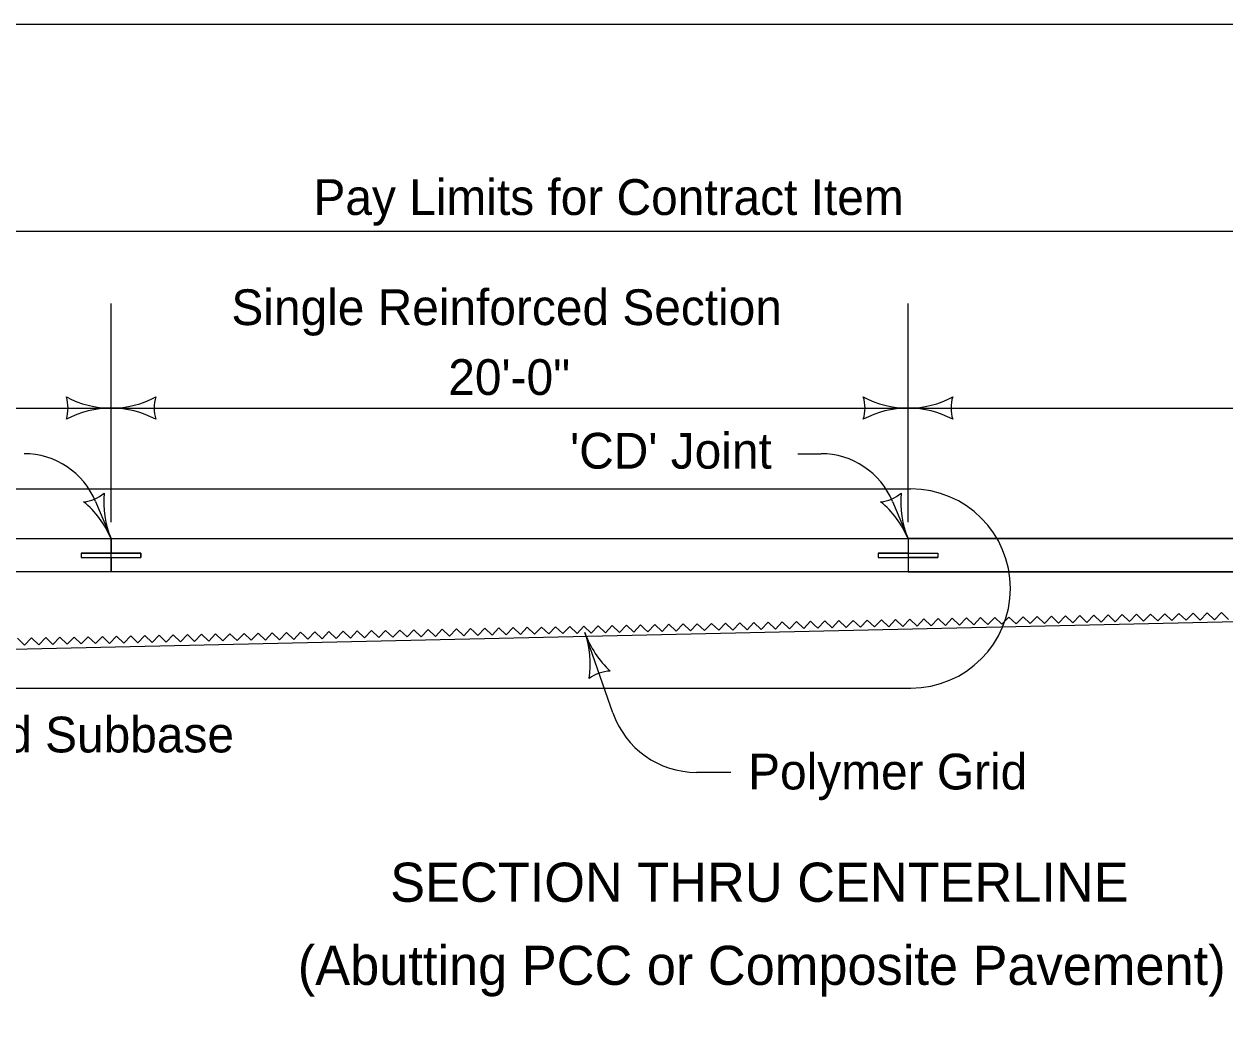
# Model space of a CAD drawing. Extents: x -2135039 to -2124495, y -2139046 to -2132546.
# Drawn here: x -2130571 to -2130034, y -2133467 to -2133016 of the extents above; entities that cross this region are included whole.
import ezdxf

# ---------------------------------------------------------------- set-up
doc = ezdxf.new("R2010")
doc.units = 0
for name, color, linetype in [('BridgeSuperStructureExisting', 7, 'Continuous'), ('dsnAlignmentStation', 7, 'Continuous'), ('dsnCellElements', 7, 'Continuous'), ('dsnStdLabel', 7, 'Continuous')]:
    doc.layers.add(name, color=color, linetype=linetype)

msp = doc.modelspace()

# ---------------------------------------------------------------- linework, layer by layer
at = {"layer": 'BridgeSuperStructureExisting'}
for p, q in [((-2130538.96, -2133229.57), (-2130532.03, -2133246.22)), ((-2130182.56, -2133229.57), (-2130175.63, -2133246.22)), ((-2130977.53, -2133246.22), (-2129822.62, -2133246.22)), ((-2130532.03, -2133261.07), (-2130532.03, -2133246.22)), ((-2129822.62, -2133246.22), (-2130175.63, -2133246.22)), ((-2130175.63, -2133246.22), (-2130175.63, -2133252.72)), ((-2130175.63, -2133246.22), (-2130175.63, -2133261.07)), ((-2130545.4, -2133252.72), (-2130518.67, -2133252.72)), ((-2130545.4, -2133252.72), (-2130545.4, -2133254.58)), ((-2130545.4, -2133254.58), (-2130518.67, -2133254.58)), ((-2130518.67, -2133252.72), (-2130518.67, -2133254.58)), ((-2130189, -2133252.72), (-2130162.27, -2133252.72)), ((-2130189, -2133252.72), (-2130189, -2133254.58)), ((-2130189, -2133254.58), (-2130162.27, -2133254.58)), ((-2130175.63, -2133252.72), (-2130162.27, -2133252.72)), ((-2130162.27, -2133254.58), (-2130175.63, -2133254.58)), ((-2130175.63, -2133254.58), (-2130175.63, -2133261.07)), ((-2130162.27, -2133252.72), (-2130162.27, -2133254.58)), ((-2130162.27, -2133252.72), (-2130162.27, -2133254.58)), ((-2129836.3, -2133261.07), (-2130977.53, -2133261.07)), ((-2130175.63, -2133261.07), (-2129836.31, -2133261.07)), ((-2129826.66, -2133278.89), (-2130943.89, -2133304.14))]:
    msp.add_line(p, q, dxfattribs=at)
for points in [[(-2130175.63, -2133246.22), (-2130175.63, -2133246.22)], [(-2130293.59, -2133286.35), (-2130291.97, -2133287.91), (-2130288.87, -2133284.67), (-2130285.64, -2133287.77), (-2130282.54, -2133284.53), (-2130279.3, -2133287.63), (-2130276.2, -2133284.4), (-2130272.97, -2133287.5), (-2130269.87, -2133284.26), (-2130266.64, -2133287.36), (-2130263.53, -2133284.13), (-2130260.3, -2133287.23), (-2130257.2, -2133284), (-2130253.96, -2133287.09), (-2130250.87, -2133283.86), (-2130247.63, -2133286.96), (-2130244.53, -2133283.72), (-2130241.3, -2133286.82), (-2130238.2, -2133283.59), (-2130234.96, -2133286.69), (-2130231.86, -2133283.45), (-2130228.63, -2133286.55), (-2130225.53, -2133283.31), (-2130222.29, -2133286.41), (-2130219.19, -2133283.18), (-2130217.57, -2133284.73)], [(-2130217.57, -2133284.73), (-2130215.96, -2133286.28), (-2130212.86, -2133283.05), (-2130209.62, -2133286.15), (-2130206.52, -2133282.91), (-2130203.29, -2133286.01), (-2130200.19, -2133282.78), (-2130196.96, -2133285.87), (-2130193.85, -2133282.64), (-2130190.62, -2133285.74), (-2130187.52, -2133282.5), (-2130184.29, -2133285.6), (-2130181.19, -2133282.37), (-2130177.95, -2133285.47), (-2130174.85, -2133282.23), (-2130171.62, -2133285.33), (-2130168.52, -2133282.09), (-2130165.28, -2133285.2), (-2130162.18, -2133281.96), (-2130158.95, -2133285.06), (-2130155.85, -2133281.83), (-2130152.61, -2133284.93), (-2130149.51, -2133281.69), (-2130146.28, -2133284.79), (-2130143.18, -2133281.56), (-2130141.56, -2133283.1)], [(-2130141.56, -2133283.1), (-2130139.94, -2133284.65), (-2130136.85, -2133281.42), (-2130133.61, -2133284.52), (-2130130.51, -2133281.28), (-2130127.28, -2133284.38), (-2130124.17, -2133281.15), (-2130120.94, -2133284.25), (-2130117.84, -2133281.01), (-2130114.61, -2133284.11), (-2130111.51, -2133280.87), (-2130108.27, -2133283.98), (-2130105.17, -2133280.74), (-2130101.94, -2133283.84), (-2130098.84, -2133280.61), (-2130095.6, -2133283.71), (-2130092.5, -2133280.47), (-2130089.27, -2133283.57), (-2130086.17, -2133280.34), (-2130082.93, -2133283.43), (-2130079.83, -2133280.2), (-2130076.6, -2133283.3), (-2130073.5, -2133280.06), (-2130070.26, -2133283.16), (-2130067.17, -2133279.93), (-2130065.55, -2133281.48)], [(-2130065.55, -2133281.48), (-2130063.93, -2133283.03), (-2130060.83, -2133279.79), (-2130057.6, -2133282.89), (-2130054.49, -2133279.65), (-2130051.26, -2133282.76), (-2130048.16, -2133279.52), (-2130044.93, -2133282.62), (-2130041.83, -2133279.39), (-2130038.59, -2133282.49), (-2130035.49, -2133279.25), (-2130032.26, -2133282.35)], [(-2130521.63, -2133291.23), (-2130520.02, -2133292.79), (-2130516.92, -2133289.55), (-2130513.68, -2133292.65), (-2130510.58, -2133289.41), (-2130507.35, -2133292.51), (-2130504.25, -2133289.28), (-2130501.01, -2133292.38), (-2130497.91, -2133289.14), (-2130494.68, -2133292.24), (-2130491.58, -2133289.01), (-2130488.34, -2133292.11), (-2130485.25, -2133288.87), (-2130482.01, -2133291.97), (-2130478.91, -2133288.74), (-2130475.68, -2133291.84), (-2130472.57, -2133288.6), (-2130469.34, -2133291.7), (-2130466.24, -2133288.47), (-2130463.01, -2133291.57), (-2130459.91, -2133288.33), (-2130456.67, -2133291.43), (-2130453.57, -2133288.19), (-2130450.34, -2133291.29), (-2130447.24, -2133288.06), (-2130445.62, -2133289.61)], [(-2130445.62, -2133289.61), (-2130444, -2133291.16), (-2130440.9, -2133287.92), (-2130437.67, -2133291.02), (-2130434.57, -2133287.79), (-2130431.33, -2133290.89), (-2130428.23, -2133287.65), (-2130425, -2133290.75), (-2130421.9, -2133287.52), (-2130418.66, -2133290.62), (-2130415.56, -2133287.38), (-2130412.33, -2133290.48), (-2130409.23, -2133287.25), (-2130406, -2133290.35), (-2130402.89, -2133287.11), (-2130399.66, -2133290.21), (-2130396.56, -2133286.97), (-2130393.33, -2133290.07), (-2130390.23, -2133286.84), (-2130386.99, -2133289.94), (-2130383.89, -2133286.7), (-2130380.66, -2133289.8), (-2130377.56, -2133286.57), (-2130374.32, -2133289.67), (-2130371.22, -2133286.43), (-2130369.61, -2133287.98)], [(-2130369.61, -2133287.98), (-2130367.99, -2133289.53), (-2130364.89, -2133286.3), (-2130361.65, -2133289.4), (-2130358.55, -2133286.16), (-2130355.32, -2133289.26), (-2130352.22, -2133286.03), (-2130348.98, -2133289.13), (-2130345.89, -2133285.89), (-2130342.65, -2133288.99), (-2130339.55, -2133285.75), (-2130336.32, -2133288.85), (-2130333.21, -2133285.62), (-2130329.98, -2133288.72), (-2130326.88, -2133285.48), (-2130323.65, -2133288.58), (-2130320.55, -2133285.35), (-2130317.31, -2133288.45), (-2130314.21, -2133285.22), (-2130310.98, -2133288.31), (-2130307.88, -2133285.08), (-2130304.64, -2133288.18), (-2130301.54, -2133284.94), (-2130298.31, -2133288.04), (-2130295.21, -2133284.81), (-2130293.59, -2133286.35)], [(-2130573.93, -2133290.77), (-2130570.69, -2133293.87), (-2130567.59, -2133290.63), (-2130564.36, -2133293.73), (-2130561.26, -2133290.5), (-2130558.02, -2133293.6), (-2130554.92, -2133290.36), (-2130551.69, -2133293.46), (-2130548.59, -2133290.23), (-2130545.36, -2133293.32), (-2130542.25, -2133290.09), (-2130539.02, -2133293.19), (-2130535.92, -2133289.96), (-2130532.69, -2133293.06), (-2130529.59, -2133289.82), (-2130526.35, -2133292.92), (-2130523.25, -2133289.69), (-2130521.63, -2133291.23)]]:
    msp.add_lwpolyline(points, dxfattribs=at)
at = {"layer": 'dsnAlignmentStation'}
msp.add_lwpolyline([(-2131334.44, -2133015.96), (-2128199.45, -2133015.96), (-2128199.45, -2135025.95), (-2131334.44, -2135025.95)], close=True, dxfattribs=at)
at = {"layer": 'dsnCellElements'}
for centre, radius, start, end in [((-2130567.66, -2133187.8), 16.42, 342.2666, 17.7333), ((-2130532.03, -2133145.3), 42.5, 241.9275, 270), ((-2130532.03, -2133145.3), 42.5, 270, 298.0725), ((-2130496.39, -2133187.8), 16.42, 162.2666, 197.7334), ((-2130211.26, -2133187.8), 16.42, 342.2666, 17.7333), ((-2130175.63, -2133145.3), 42.5, 241.9275, 270), ((-2130175.63, -2133145.3), 42.5, 270, 298.0725), ((-2130139.99, -2133187.8), 16.42, 162.2666, 197.7334), ((-2130532.03, -2133230.3), 42.5, 90, 118.0725), ((-2130532.03, -2133230.3), 42.5, 61.9275, 90), ((-2130175.63, -2133230.3), 42.5, 90, 118.0725), ((-2130175.63, -2133230.3), 42.5, 61.9275, 90), ((-2130545.72, -2133213.33), 16.42, 274.8653, 310.332), ((-2130571.27, -2133262.56), 42.5, 22.5986, 50.6711), ((-2130492.79, -2133229.89), 42.5, 174.5261, 202.5986), ((-2130189.32, -2133213.33), 16.42, 274.8653, 310.332), ((-2130214.87, -2133262.56), 42.5, 22.5986, 50.6711), ((-2130136.39, -2133229.89), 42.5, 174.5261, 202.5986), ((-2130279.95, -2133274.29), 42.5, 199.1744, 227.2469), ((-2130360.24, -2133302.21), 42.5, 351.1019, 19.1744), ((-2130308.39, -2133321.91), 16.42, 91.4411, 126.9078)]:
    msp.add_arc(centre, radius, start, end, dxfattribs=at)
at = {"layer": 'dsnStdLabel'}
for p, q in [((-2130980.5, -2133108.6), (-2129641.03, -2133108.6)), ((-2130532.03, -2133238.8), (-2130532.03, -2133141.06)), ((-2130175.63, -2133238.8), (-2130175.63, -2133141.06)), ((-2130980.5, -2133187.8), (-2130532.03, -2133187.8)), ((-2130532.03, -2133187.8), (-2130175.63, -2133187.8)), ((-2130175.63, -2133187.8), (-2129819.23, -2133187.8)), ((-2130224.9, -2133208.22), (-2130214.56, -2133208.22)), ((-2130977.53, -2133223.95), (-2130174.37, -2133223.95)), ((-2130977.53, -2133246.22), (-2130532.03, -2133246.22)), ((-2130532.03, -2133246.22), (-2130532.03, -2133252.71)), ((-2130532.03, -2133252.71), (-2130532.03, -2133246.22)), ((-2130532.03, -2133246.22), (-2130175.63, -2133246.22)), ((-2130175.63, -2133246.22), (-2130175.63, -2133252.72)), ((-2130532.03, -2133252.71), (-2130545.4, -2133252.72)), ((-2130545.4, -2133252.72), (-2130532.03, -2133252.71)), ((-2130545.4, -2133252.72), (-2130545.4, -2133254.58)), ((-2130518.67, -2133252.72), (-2130545.4, -2133252.72)), ((-2130545.4, -2133254.58), (-2130532.05, -2133254.58)), ((-2130532.05, -2133254.58), (-2130532.03, -2133261.07)), ((-2130532.03, -2133261.07), (-2130532.05, -2133254.58)), ((-2130532.03, -2133254.61), (-2130518.67, -2133254.58)), ((-2130518.67, -2133254.58), (-2130518.67, -2133252.72)), ((-2130175.63, -2133252.72), (-2130189, -2133252.72)), ((-2130189, -2133252.72), (-2130189, -2133254.58)), ((-2130189, -2133254.58), (-2130175.63, -2133254.58)), ((-2130175.63, -2133254.58), (-2130175.63, -2133261.07)), ((-2130532.03, -2133261.07), (-2130940.4, -2133261.07)), ((-2130175.63, -2133261.07), (-2130532.03, -2133261.07)), ((-2130307.6, -2133324.19), (-2130320.09, -2133288.25)), ((-2130977.53, -2133313.05), (-2130174.37, -2133313.05)), ((-2130254.86, -2133350.78), (-2130270.19, -2133350.78))]:
    msp.add_line(p, q, dxfattribs=at)
for centre, radius, start, end in [((-2130570.95, -2133242.87), 34.65, 22.5907, 90), ((-2130214.55, -2133242.87), 34.65, 22.5907, 90), ((-2130174.37, -2133268.5), 44.55, 270.0011, 90), ((-2130270.19, -2133311.18), 39.6, 199.1769, 270)]:
    msp.add_arc(centre, radius, start, end, dxfattribs=at)

# ---------------------------------------------------------------- texts
at = {"layer": 'BridgeSuperStructureExisting'}
msp.add_text('SECTION THRU CENTERLINE', height=17.5, dxfattribs=at).set_placement((-2130407.22, -2133408.68))
at = {"layer": 'dsnStdLabel'}
for s, height, p in [('Pay Limits for Contract Item', 16, (-2130441.52, -2133101.39)), ('Single Reinforced Section', 16, (-2130478.22, -2133150.67)), ('20\'-0"', 16, (-2130381.23, -2133181.92)), ("'CD' Joint", 16, (-2130326.76, -2133214.89)), ('Modified Subbase', 16, (-2130648.33, -2133341.86)), ('Polymer Grid', 16, (-2130247.14, -2133358.43)), ('(Abutting PCC or Composite Pavement)', 17.5, (-2130448.52, -2133445.86))]:
    msp.add_text(s, height=height, dxfattribs=at).set_placement(p)

doc.saveas('drawing.dxf')
